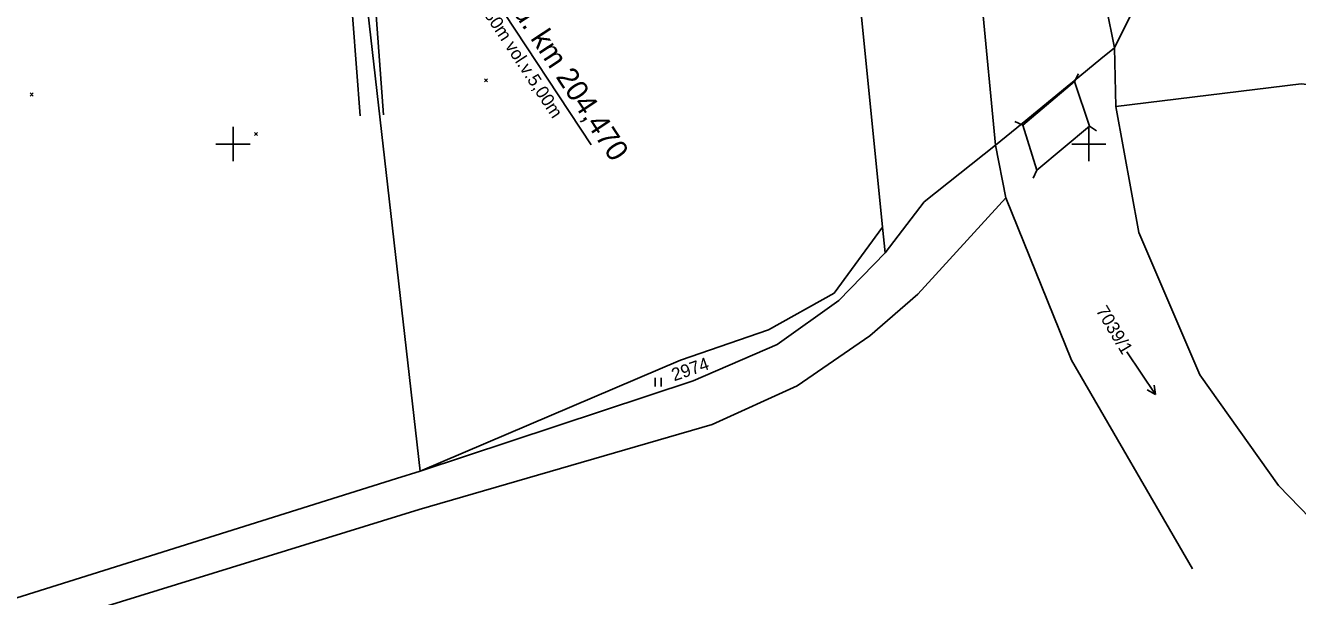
# Model space of a CAD drawing. Extents: x -800194 to -799078, y -1007177 to -1006597.
# Drawn here: x -799524.3 to -799375.6, y -1007052.9 to -1006986.1 of the extents above; entities that cross this region are included whole.
import ezdxf

# ---------------------------------------------------------------- set-up
doc = ezdxf.new("R2010")
doc.units = 0
for name, color, linetype in [('02_Osa_koleje', 7, 'Continuous'), ('Ramove udaje', 7, 'Continuous'), ('Vrstva 18', 7, 'Continuous'), ('Vrstva 49', 7, 'Continuous'), ('Vrstva 51', 7, 'Continuous'), ('Vrstva 55', 7, 'Continuous'), ('Vrstva 56', 7, 'Continuous'), ('Vrstva 57', 7, 'Continuous'), ('Vrstva 58', 7, 'Continuous')]:
    doc.layers.add(name, color=color, linetype=linetype)

msp = doc.modelspace()

# ---------------------------------------------------------------- linework, layer by layer
at = {"layer": '02_Osa_koleje'}
msp.add_arc((-799651.02, -1006703.89), 292, 255.6249, 308.2052, dxfattribs=at)
at = {"layer": 'Ramove udaje'}
for p, q in [((-799500, -1006998), (-799500, -1007002)), ((-799400, -1006998), (-799400, -1007002)), ((-799502, -1007000), (-799500, -1007000)), ((-799500, -1007000), (-799498, -1007000)), ((-799402, -1007000), (-799400, -1007000)), ((-799400, -1007000), (-799398, -1007000))]:
    msp.add_line(p, q, dxfattribs=at)
at = {"layer": 'Vrstva 18'}
msp.add_line((-799458.17, -1007000.07), (-799490.2, -1006951.4), dxfattribs=at)
at = {"layer": 'Vrstva 49'}
for p, q in [((-799470.61, -1006992.35), (-799470.26, -1006992.71)), ((-799470.61, -1006992.71), (-799470.26, -1006992.35)), ((-799523.7, -1006994.02), (-799523.35, -1006994.38)), ((-799523.7, -1006994.38), (-799523.35, -1006994.02)), ((-799497.49, -1006998.64), (-799497.14, -1006998.99)), ((-799497.49, -1006998.99), (-799497.14, -1006998.64))]:
    msp.add_line(p, q, dxfattribs=at)
at = {"layer": 'Vrstva 51'}
for points in [[(-799485.17, -1006996.71), (-799487.28, -1006968.61)], [(-799482.42, -1006996.56), (-799484.49, -1006968.49)]]:
    msp.add_lwpolyline(points, dxfattribs=at)
at = {"layer": 'Vrstva 55'}
for p, q in [((-799424.1, -1007009.73), (-799433.4, -1006916.39)), ((-799487.22, -1006958.47), (-799478.14, -1007038.23)), ((-799397.01, -1006988.73), (-799398.6, -1006990.04)), ((-799397.01, -1006988.73), (-799396.86, -1006995.59)), ((-799409.68, -1007006.29), (-799410.89, -1007000.14)), ((-799424.1, -1007009.73), (-799423.8, -1007012.71))]:
    msp.add_line(p, q, dxfattribs=at)
for points in [[(-799413.75, -1006898.23), (-799411.99, -1006904.75), (-799406.72, -1006940.36), (-799397.01, -1006988.73)], [(-799410.89, -1007000.14), (-799412.5, -1006983.38), (-799423.07, -1006906.83)], [(-799397.01, -1006988.73), (-799388.9, -1006972.36), (-799387.62, -1006968.78)], [(-799398.6, -1006990.04), (-799401.7, -1006992.59), (-799402.52, -1006993.26), (-799407.79, -1006997.59), (-799410.89, -1007000.14)], [(-799312.4, -1007006.62), (-799318.99, -1007006.15), (-799364.52, -1006994.13), (-799375.17, -1006992.97), (-799396.86, -1006995.59)], [(-799396.86, -1006995.59), (-799394.17, -1007010.32), (-799387.01, -1007026.98), (-799377.82, -1007039.94), (-799372.89, -1007045.05)], [(-799423.8, -1007012.71), (-799419.24, -1007006.74), (-799410.89, -1007000.14)], [(-799409.68, -1007006.29), (-799420, -1007017.54), (-799425.58, -1007022.42), (-799434.1, -1007028.26), (-799444.02, -1007032.78), (-799478.24, -1007042.75), (-799552.64, -1007065.71), (-799567.11, -1007070.01), (-799588.9, -1007077.33), (-799598.09, -1007080.87), (-799606.31, -1007085.7)], [(-799387.89, -1007049.68), (-799402.01, -1007025.25), (-799409.68, -1007006.29)], [(-799478.14, -1007038.23), (-799447.72, -1007025.26), (-799437.44, -1007021.73), (-799429.75, -1007017.42), (-799424.1, -1007009.73)], [(-799478.14, -1007038.23), (-799446.24, -1007027.7), (-799436.41, -1007023.44), (-799429.23, -1007018.29), (-799423.8, -1007012.71)], [(-799584.37, -1007069.36), (-799568.78, -1007065.44), (-799553.44, -1007061.89), (-799480.9, -1007039.1), (-799478.14, -1007038.23)]]:
    msp.add_lwpolyline(points, dxfattribs=at)
at = {"layer": 'Vrstva 56'}
for p, q in [((-799401.22, -1006991.8), (-799401.66, -1006992.7)), ((-799401.66, -1006992.7), (-799407.73, -1006997.77)), ((-799401.66, -1006992.7), (-799399.93, -1006997.9)), ((-799408.64, -1006997.35), (-799407.73, -1006997.77)), ((-799407.73, -1006997.77), (-799406.07, -1007003.06)), ((-799399.93, -1006997.9), (-799406.07, -1007003.06)), ((-799399.1, -1006998.46), (-799399.93, -1006997.9)), ((-799406.49, -1007003.97), (-799406.07, -1007003.06))]:
    msp.add_line(p, q, dxfattribs=at)
at = {"layer": 'Vrstva 58'}
for p, q in [((-799395.57, -1007024.31), (-799392.21, -1007029.28)), ((-799450.66, -1007028.34), (-799450.66, -1007027.34)), ((-799449.99, -1007028.34), (-799449.99, -1007027.34)), ((-799392.21, -1007029.28), (-799392.35, -1007028.19)), ((-799392.21, -1007029.28), (-799393.18, -1007028.75))]:
    msp.add_line(p, q, dxfattribs=at)

# ---------------------------------------------------------------- texts
at = {"layer": 'Vrstva 18'}
for s, height, p in [('sv.kol.3,80m vol.v.5,00m', 1.5, (-799474.77, -1006978.68)), ('evid. km 204,470', 2.5, (-799469.71, -1006980.95))]:
    msp.add_text(s, height=height, rotation=303.3554, dxfattribs=at).set_placement(p)
at = {"layer": 'Vrstva 57'}
for s, rotation, p in [('7039/1', 301, (-799399.22, -1007019.47)), ('2974', 19, (-799448.46, -1007027.75))]:
    msp.add_text(s, height=1.5, rotation=rotation, dxfattribs=at).set_placement(p)

doc.saveas('drawing.dxf')
